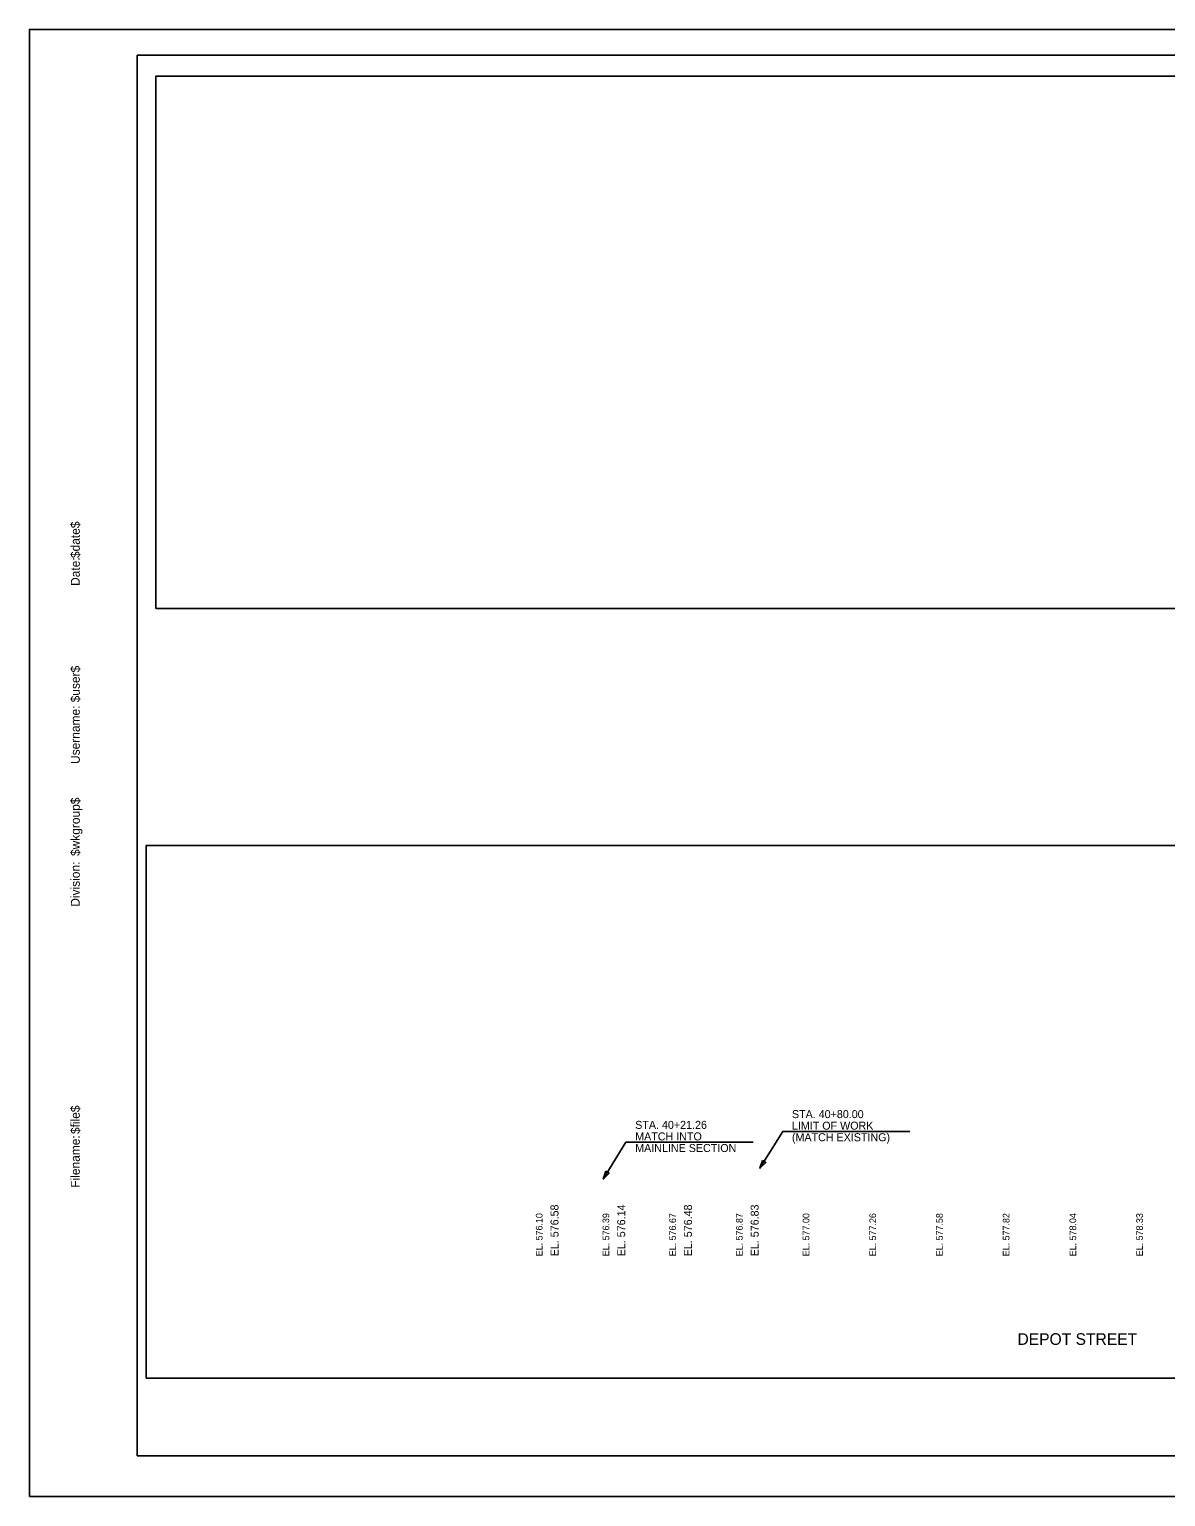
# Model space of a CAD drawing. Extents: x 1041423 to 1042273, y 773317 to 773867.
# Drawn here: x 1041423 to 1041849, y 773317 to 773867 of the extents above; entities that cross this region are included whole.
import ezdxf

# ---------------------------------------------------------------- set-up
doc = ezdxf.new("R2010")
doc.units = 0
for name, color, linetype in [('ANNOTATION', 7, 'Continuous'), ('CLIPS', 7, 'Continuous'), ('D_Roadway_Centerline_CurveData', 7, 'Continuous'), ('D_Roadway_Centerline_Text', 7, 'Continuous'), ('Default', 7, 'Continuous'), ('H_V ANNOTATION', 7, 'Continuous'), ('PLOT BOUNDARY', 7, 'Continuous')]:
    doc.layers.add(name, color=color, linetype=linetype)

msp = doc.modelspace()

# ---------------------------------------------------------------- linework, layer by layer
at = {"layer": 'CLIPS'}
for points in [[(1041470.67, 773649.42), (1042209.45, 773649.42), (1042209.45, 773849.01), (1041470.67, 773849.01)], [(1041466.97, 773360.98), (1042205.76, 773360.98), (1042205.76, 773560.57), (1041466.97, 773560.57)]]:
    msp.add_lwpolyline(points, close=True, dxfattribs=at)
at = {"layer": 'D_Roadway_Centerline_CurveData'}
for points in [[(1041697.05, 773439.62), (1041705.58, 773453.4), (1041753.25, 773453.4)], [(1041638.31, 773435.59), (1041646.84, 773449.37), (1041694.51, 773449.37)]]:
    msp.add_lwpolyline(points, dxfattribs=at)
for points in [[(1041697.99, 773442.56), (1041697.05, 773439.62), (1041699.27, 773441.77)], [(1041639.25, 773438.53), (1041638.31, 773435.59), (1041640.53, 773437.74)]]:
    msp.add_lwpolyline(points, close=True, dxfattribs=at)
at = {"layer": 'Default'}
for p, q in [((1042263.7, 773856.84), (1041463.7, 773856.84)), ((1041463.7, 773856.84), (1041463.7, 773331.84)), ((1041463.7, 773331.84), (1042263.7, 773331.84))]:
    msp.add_line(p, q, dxfattribs=at)
at = {"layer": 'PLOT BOUNDARY'}
msp.add_lwpolyline([(1041423.24, 773316.54), (1042273.23, 773316.54), (1042273.23, 773866.54), (1041423.24, 773866.54)], close=True, dxfattribs=at)

# ---------------------------------------------------------------- texts
at = {"layer": 'ANNOTATION'}
for s, p in [('EL. 576.10', (1041615.55, 773406.64)), ('EL. 576.39', (1041640.55, 773406.64)), ('EL. 576.67', (1041665.55, 773406.64)), ('EL. 576.87', (1041690.55, 773406.64)), ('EL. 577.00', (1041715.55, 773406.64)), ('EL. 577.26', (1041740.55, 773406.64)), ('EL. 577.58', (1041765.55, 773406.64)), ('EL. 577.82', (1041790.55, 773406.64)), ('EL. 578.04', (1041815.55, 773406.64)), ('EL. 578.33', (1041840.55, 773406.64))]:
    msp.add_text(s, height=2.5, rotation=90, dxfattribs=at).set_placement(p)
at = {"layer": 'D_Roadway_Centerline_CurveData'}
for s, p in [('STA. 40+80.00', (1041709.03, 773458.43)), ('STA. 40+21.26', (1041650.29, 773454.4)), ('MATCH INTO', (1041650.29, 773450.07)), ('(MATCH EXISTING)', (1041709.03, 773449.76)), ('LIMIT OF WORK', (1041709.03, 773454.1)), ('MAINLINE SECTION', (1041650.29, 773445.73))]:
    msp.add_text(s, height=3, dxfattribs=at).set_placement(p)
at = {"layer": 'D_Roadway_Centerline_Text'}
for s, p in [('EL. 576.58', (1041621.55, 773406.64)), ('EL. 576.14', (1041646.55, 773406.64)), ('EL. 576.48', (1041671.55, 773406.64)), ('EL. 576.83', (1041696.55, 773406.64))]:
    msp.add_text(s, height=3, rotation=90, dxfattribs=at).set_placement(p)
at = {"layer": 'Default'}
for s, p in [('$date$', (1041442.13, 773668.36)), ('Date:', (1041442.13, 773657.92)), ('$user$', (1041442.13, 773614.29)), ('Username:', (1041442.13, 773591.18)), ('$wkgroup$', (1041442.13, 773556.68)), ('Division:', (1041442.13, 773537.67)), ('$file$', (1041442.13, 773452.46)), ('Filename:', (1041442.13, 773432.33))]:
    msp.add_text(s, height=3.348, rotation=90, dxfattribs=at).set_placement(p)
at = {"layer": 'H_V ANNOTATION'}
msp.add_text('DEPOT STREET', height=4.3749, dxfattribs=at).set_placement((1041793.55, 773373.42))

doc.saveas('drawing.dxf')
